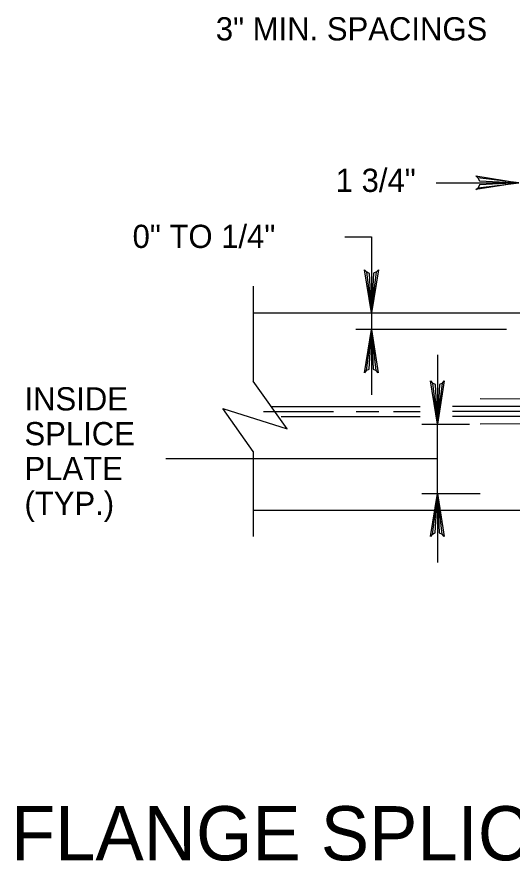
# Model space of a CAD drawing. Extents: x 638466 to 639375, y 297808 to 298996.
# Drawn here: x 638864.6 to 638933.7, y 298102.1 to 298219.9 of the extents above; entities that cross this region are included whole.
import ezdxf

# ---------------------------------------------------------------- set-up
doc = ezdxf.new("R2010")
doc.units = 0
for name, color, linetype in [('1', 7, 'Continuous'), ('2', 7, 'Continuous'), ('4', 7, 'Continuous')]:
    doc.layers.add(name, color=color, linetype=linetype)

msp = doc.modelspace()

# ---------------------------------------------------------------- linework, layer by layer
at = {"layer": '1'}
for points in [[(638928.97, 298197.49), (638929.18, 298197.07), (638934.69, 298196.77), (638928.97, 298197.49), (638928.68, 298197.74), (638934.69, 298196.77), (638929.19, 298196.5), (638928.99, 298196.09), (638934.69, 298196.77), (638928.68, 298195.82), (638928.99, 298196.09)], [(638914.82, 298184.36), (638914.41, 298184.15), (638914.1, 298178.64), (638914.82, 298184.36), (638915.07, 298184.65), (638914.1, 298178.64), (638913.83, 298184.14), (638913.42, 298184.35), (638914.1, 298178.64), (638913.15, 298184.65), (638913.42, 298184.35)], [(638913.38, 298170.56), (638913.8, 298170.77), (638914.1, 298176.28), (638913.38, 298170.56), (638913.13, 298170.26), (638914.1, 298176.28), (638914.37, 298170.78), (638914.78, 298170.57), (638914.1, 298176.28), (638915.05, 298170.26), (638914.78, 298170.57)], [(638924.03, 298168.82), (638923.61, 298168.61), (638923.31, 298163.1), (638924.03, 298168.82), (638924.28, 298169.12), (638923.31, 298163.1), (638923.04, 298168.61), (638922.63, 298168.81), (638923.31, 298163.1), (638922.35, 298169.12), (638922.63, 298168.81)], [(638922.59, 298147.72), (638923.01, 298147.93), (638923.31, 298153.44), (638922.59, 298147.72), (638922.34, 298147.43), (638923.31, 298153.44), (638923.58, 298147.94), (638923.99, 298147.74), (638923.31, 298153.44), (638924.26, 298147.43), (638923.99, 298147.74)]]:
    msp.add_lwpolyline(points, dxfattribs=at)
at = {"layer": '2'}
for p, q in [((638897.61, 298182.34), (638897.61, 298169.09)), ((638897.61, 298178.64), (638967.29, 298178.64)), ((638902.33, 298162.45), (638897.61, 298169.09)), ((639007.65, 298166.38), (638929.3, 298166.62)), ((638897.61, 298159.3), (638893.35, 298165.29)), ((638893.35, 298165.29), (638902.33, 298162.45)), ((638900.11, 298165.57), (638920.91, 298165.57)), ((639010.8, 298165.57), (638925.4, 298165.57)), ((638899.04, 298164.86), (638908.82, 298164.86)), ((638901.5, 298164.16), (638920.91, 298164.16)), ((638911.98, 298164.86), (638915.13, 298164.86)), ((638917.2, 298164.86), (638920.91, 298164.86)), ((638993.8, 298164.86), (638925.4, 298164.86)), ((639010.8, 298164.16), (638925.4, 298164.16)), ((639007.65, 298163.35), (638929.3, 298163.1)), ((638897.61, 298159.3), (638897.61, 298147.4)), ((638897.61, 298151.08), (638967.29, 298151.08))]:
    msp.add_line(p, q, dxfattribs=at)
at = {"layer": '4'}
for p, q in [((638923.14, 298196.77), (638934.69, 298196.77)), ((638910.41, 298189.23), (638914.1, 298189.23)), ((638914.1, 298189.23), (638914.1, 298167.2)), ((638932.96, 298176.28), (638911.95, 298176.28)), ((638923.31, 298172.76), (638923.31, 298163.1)), ((638921.13, 298163.1), (638927.78, 298163.1)), ((638923.31, 298153.44), (638923.31, 298163.1)), ((638923.31, 298158.27), (638885.41, 298158.27)), ((638921.13, 298153.44), (638929.3, 298153.44)), ((638923.31, 298153.44), (638923.31, 298143.78))]:
    msp.add_line(p, q, dxfattribs=at)

# ---------------------------------------------------------------- texts
for s, height, p in [('3" MIN. SPACINGS', 3.24, (638892.38, 298216.64)), ('1 3/4"', 3.24, (638909.12, 298195.5)), ('0" TO 1/4"', 3.24, (638880.76, 298187.68)), ('INSIDE', 3.24, (638865.67, 298165.01)), ('SPLICE', 3.24, (638865.67, 298160.15)), ('PLATE', 3.24, (638865.67, 298155.29)), ('(TYP.)', 3.24, (638865.67, 298150.43)), ('FLANGE SPLICE DETAIL - TYPE 2', 7.56, (638863.78, 298102.23))]:
    msp.add_text(s, height=height, dxfattribs=at).set_placement(p)

doc.saveas('drawing.dxf')
